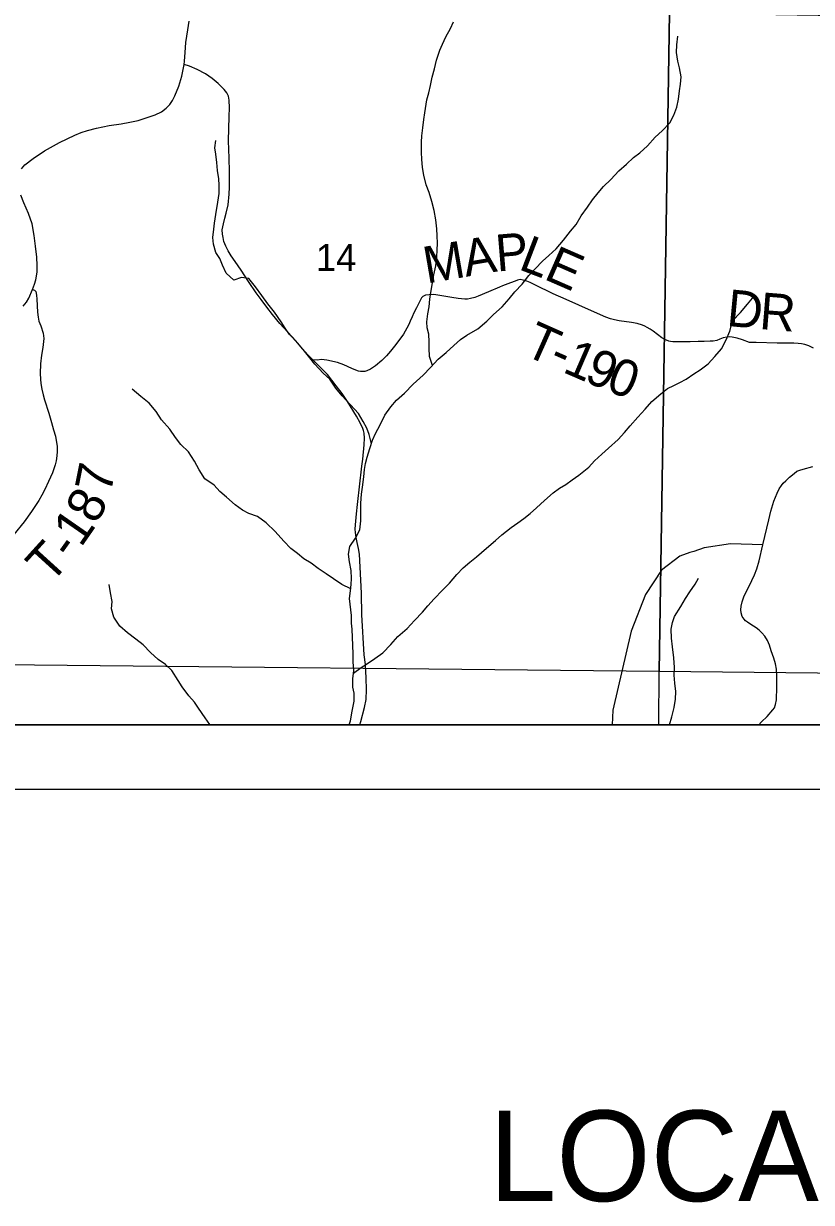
# Model space of a CAD drawing. Extents: x 0 to 34, y -8.9 to 22.
# Drawn here: x 25.687 to 26.904, y 6.366 to 8.187 of the extents above; entities that cross this region are included whole.
import ezdxf

# ---------------------------------------------------------------- set-up
doc = ezdxf.new("R2010")
doc.units = 0
for name, color, linetype in [('GM_X_Corporation', 7, 'Continuous'), ('GM_X_County_Road', 7, 'Continuous'), ('GM_X_Minor_River', 7, 'Continuous'), ('GM_X_Section_Text', 7, 'Continuous'), ('GM_X_State_Route', 7, 'Continuous'), ('GM_X_Township_Road', 7, 'Continuous'), ('GM_X_Township_Road_Text', 7, 'Continuous'), ('SH_Data', 7, 'Continuous'), ('SH_Text', 7, 'Continuous')]:
    doc.layers.add(name, color=color, linetype=linetype)

msp = doc.modelspace()

# ---------------------------------------------------------------- linework, layer by layer
at = {"layer": 'GM_X_Corporation'}
for points in [[(23.7167, 11.9654), (23.7167, 7.104), (28.7046, 7.104), (28.7123, 8.2818), (28.7238, 9.1729), (28.7308, 9.4444), (28.7377, 10.2012)], [(24.1844, 10.755), (24.1596, 9.2636), (24.0743, 9.2644), (23.7167, 9.2682), (23.7167, 7.104), (28.7046, 7.104), (28.7123, 8.2818), (28.7238, 9.1729), (28.7308, 9.4444), (28.7377, 10.2012)]]:
    msp.add_lwpolyline(points, dxfattribs=at)
for points in [[(25.6692, 8.2169), (26.6846, 8.2041), (26.6684, 7.1864), (25.6523, 7.1969)], [(26.6846, 8.2041), (27.7031, 8.1879), (27.6975, 7.1757), (26.6684, 7.1864)], [(25.6521, 7.104), (26.6681, 7.104), (26.6684, 7.1864), (25.6523, 7.1969)]]:
    msp.add_lwpolyline(points, close=True, dxfattribs=at)
at = {"layer": 'GM_X_County_Road'}
msp.add_lwpolyline([(26.206, 7.104), (26.2077, 7.1091), (26.2134, 7.1305), (26.2158, 7.1431), (26.2164, 7.1587), (26.216, 7.1759), (26.2148, 7.197), (26.213, 7.2119), (26.2093, 7.2739), (26.2085, 7.3075), (26.2055, 7.3679), (26.2043, 7.3764), (26.2021, 7.3857), (26.2003, 7.3935), (26.1992, 7.4009), (26.199, 7.4061), (26.1993, 7.4128), (26.2011, 7.43), (26.2027, 7.4445), (26.2059, 7.4764), (26.2085, 7.4988), (26.2091, 7.5035), (26.2107, 7.5147), (26.213, 7.5366), (26.2135, 7.5467), (26.2127, 7.5548), (26.2117, 7.5588), (26.2107, 7.5619), (26.2067, 7.5706), (26.2009, 7.5809), (26.1868, 7.6037), (26.1787, 7.616), (26.1696, 7.6279), (26.1563, 7.6451), (26.143, 7.6588), (26.1334, 7.6678), (26.126, 7.6755), (26.1173, 7.6851), (26.107, 7.6973), (26.0826, 7.7241), (26.0711, 7.7379), (26.0624, 7.7491), (26.0535, 7.761), (26.0457, 7.7715), (26.0343, 7.7887), (26.0228, 7.8063), (26.0135, 7.8199), (26.0073, 7.8285), (26.0028, 7.8363), (25.9988, 7.8438), (25.996, 7.8509), (25.9948, 7.8567), (25.9939, 7.862), (25.9936, 7.8687), (25.9952, 7.8779), (25.9975, 7.8867), (25.9997, 7.8943), (26.0024, 7.9074), (26.0042, 7.9241), (26.0046, 7.9347), (26.0046, 7.9442), (26.0045, 7.959), (26.0041, 7.9793), (26.0034, 8.0065), (26.0043, 8.0441), (26.0048, 8.0574), (26.0043, 8.069), (26.0031, 8.0755), (26.0006, 8.0806), (25.9965, 8.0856), (25.987, 8.0948), (25.9777, 8.1026), (25.9677, 8.1097), (25.9546, 8.1165), (25.943, 8.1217), (25.9346, 8.1244)], dxfattribs=at)
at = {"layer": 'GM_X_Minor_River'}
for points in [[(26.3183, 7.6594), (26.314, 7.6733), (26.3135, 7.6858), (26.3131, 7.6957), (26.3127, 7.7075), (26.3104, 7.7173), (26.3097, 7.7268), (26.3112, 7.739), (26.313, 7.7496), (26.3145, 7.7614), (26.316, 7.772), (26.3186, 7.7868), (26.3205, 7.799), (26.3235, 7.813), (26.325, 7.8271), (26.3257, 7.8373), (26.3261, 7.848), (26.3257, 7.8593), (26.3253, 7.8704), (26.3237, 7.884), (26.321, 7.8984), (26.3176, 7.9125), (26.313, 7.9265), (26.3088, 7.9382), (26.305, 7.9534), (26.3027, 7.9652), (26.3019, 7.9781), (26.3015, 7.9883), (26.3015, 8.0043), (26.3018, 8.0138), (26.3033, 8.0263), (26.3048, 8.0392), (26.3067, 8.0498), (26.3097, 8.0696), (26.3127, 8.0806), (26.3153, 8.092), (26.3179, 8.1045), (26.3217, 8.1174), (26.3247, 8.1311), (26.3296, 8.1463), (26.3338, 8.1558), (26.339, 8.1669), (26.3462, 8.1798), (26.3508, 8.19)], [(26.5094, 7.8394), (26.5207, 7.8528), (26.5317, 7.8665), (26.5404, 7.8771), (26.548, 7.8904), (26.5578, 7.9037), (26.5654, 7.9152), (26.5745, 7.9262), (26.5824, 7.9357), (26.5938, 7.9464), (26.6063, 7.9601), (26.618, 7.97), (26.629, 7.9806), (26.6388, 7.9875), (26.6506, 7.9986), (26.6627, 8.0119), (26.6733, 8.0218), (26.685, 8.0343), (26.6914, 8.0461), (26.696, 8.0583), (26.6986, 8.0708), (26.7001, 8.0837), (26.7016, 8.0936), (26.7027, 8.1054), (26.7, 8.119), (26.6973, 8.1293), (26.6954, 8.1429), (26.6958, 8.1547), (26.6976, 8.168)], [(26.2241, 7.5382), (26.2205, 7.5523), (26.2167, 7.5622), (26.2113, 7.5728), (26.2041, 7.5849), (26.179, 7.6121), (26.1691, 7.6243), (26.1596, 7.6383), (26.1493, 7.6474), (26.1368, 7.6614), (26.1288, 7.6712), (26.1208, 7.6814), (26.1105, 7.6939), (26.0976, 7.7072), (26.0907, 7.717), (26.0843, 7.7265), (26.074, 7.7416), (26.0637, 7.7545), (26.0546, 7.7674), (26.0447, 7.7806), (26.0344, 7.7935), (26.0234, 7.795), (26.0113, 7.7911), (25.9995, 7.8017), (25.9941, 7.8142), (25.9896, 7.8245), (25.9838, 7.834), (25.98, 7.8468), (25.9789, 7.8571), (25.9804, 7.8696), (25.9815, 7.8791), (25.9837, 7.8924), (25.9867, 7.9114), (25.9886, 7.9247), (25.9889, 7.938), (25.9882, 7.9478), (25.9862, 7.9607), (25.9851, 7.9729), (25.9835, 7.9858), (25.982, 7.9953), (25.9835, 8.007)], [(26.1897, 7.104), (26.1915, 7.1104), (26.1941, 7.1252), (26.1975, 7.1404), (26.1975, 7.1529), (26.1955, 7.1624), (26.1955, 7.1749), (26.1966, 7.1878), (26.1958, 7.2011), (26.1958, 7.2133), (26.1954, 7.2269), (26.195, 7.2387), (26.1942, 7.2516), (26.1934, 7.2611), (26.1934, 7.2728), (26.1903, 7.2994), (26.1918, 7.3112), (26.1925, 7.3207), (26.1933, 7.3302), (26.1925, 7.3423), (26.1902, 7.3556), (26.1886, 7.3677), (26.1905, 7.3795), (26.1992, 7.3924), (26.206, 7.4054), (26.2079, 7.419), (26.2078, 7.4464), (26.2086, 7.4604), (26.21, 7.4714), (26.2123, 7.487), (26.2134, 7.4984), (26.2149, 7.5079), (26.2172, 7.5177), (26.2217, 7.5311), (26.2258, 7.5436), (26.2304, 7.5542), (26.2375, 7.5675), (26.2447, 7.5824), (26.2542, 7.5953), (26.2629, 7.6056), (26.275, 7.6166), (26.2886, 7.6303), (26.3041, 7.6441), (26.3151, 7.6559), (26.3269, 7.6688), (26.3394, 7.6791), (26.3515, 7.6901), (26.3617, 7.6993), (26.3716, 7.7058), (26.3882, 7.7157), (26.4026, 7.7279), (26.4128, 7.7378), (26.4261, 7.7496), (26.4371, 7.7621), (26.4458, 7.7732), (26.4571, 7.785), (26.467, 7.7983), (26.4772, 7.8086), (26.4882, 7.8204), (26.4984, 7.8292), (26.5094, 7.8394)], [(26.1963, 7.184), (26.2084, 7.1928), (26.2179, 7.1985), (26.2292, 7.2062), (26.2417, 7.2153), (26.2538, 7.2282), (26.2648, 7.2404), (26.2792, 7.2526), (26.2906, 7.2652), (26.3027, 7.2781), (26.311, 7.288), (26.3208, 7.2987), (26.3341, 7.312), (26.3447, 7.3231), (26.3561, 7.336), (26.3659, 7.3463), (26.3761, 7.3554), (26.3863, 7.3634), (26.4019, 7.3768), (26.4159, 7.389), (26.4257, 7.3973), (26.4401, 7.4091), (26.45, 7.416), (26.4595, 7.4229), (26.4693, 7.4305), (26.4791, 7.4393), (26.4913, 7.4507), (26.5049, 7.4625), (26.5144, 7.4697), (26.5246, 7.4755), (26.5341, 7.4823), (26.5443, 7.4896), (26.5602, 7.5021), (26.5689, 7.5117), (26.5803, 7.5223), (26.5905, 7.5315), (26.6053, 7.5448), (26.6151, 7.5555), (26.6238, 7.5657), (26.6356, 7.5794), (26.6469, 7.5916), (26.6571, 7.6034), (26.6711, 7.6156), (26.6814, 7.6236), (26.6912, 7.6282), (26.7007, 7.6328), (26.7106, 7.6381), (26.7223, 7.6465), (26.7318, 7.6523), (26.7443, 7.6618), (26.7545, 7.6732), (26.7651, 7.685), (26.7723, 7.6987), (26.7776, 7.7124), (26.7821, 7.728), (26.7942, 7.7413), (26.8052, 7.7538), (26.8154, 7.7664)], [(26.192, 7.3142), (26.1785, 7.3206), (26.1656, 7.3293), (26.1542, 7.3372), (26.1416, 7.3456), (26.131, 7.3535), (26.1196, 7.3607), (26.1097, 7.3686), (26.0995, 7.3765), (26.0888, 7.3875), (26.0755, 7.4027), (26.0614, 7.4163), (26.0481, 7.4257), (26.0348, 7.4306), (26.0249, 7.4355), (26.0135, 7.4438), (25.9999, 7.4556), (25.99, 7.4643), (25.9808, 7.4741), (25.9664, 7.4843), (25.958, 7.4979), (25.9504, 7.5116), (25.9413, 7.5256), (25.9295, 7.5369), (25.9215, 7.5479), (25.9124, 7.5608), (25.8998, 7.5752), (25.8914, 7.5881), (25.8804, 7.6009), (25.8678, 7.6115), (25.8542, 7.6225)], [(26.6848, 7.104), (26.6882, 7.1165), (26.6919, 7.1306), (26.6938, 7.1435), (26.6942, 7.1556), (26.693, 7.1685), (26.6918, 7.1807), (26.6922, 7.1928), (26.6914, 7.2076), (26.6895, 7.2243), (26.6879, 7.238), (26.6871, 7.2517), (26.689, 7.2619), (26.6924, 7.2714), (26.7022, 7.2866), (26.7094, 7.2992), (26.7162, 7.3094), (26.7242, 7.3212), (26.7294, 7.3307)], [(25.9747, 7.104), (25.9745, 7.1044), (25.9672, 7.1146), (25.9569, 7.1297), (25.9508, 7.1392), (25.9421, 7.149), (25.9314, 7.1627), (25.9253, 7.1725), (25.9155, 7.1877), (25.9059, 7.1971), (25.8945, 7.2047), (25.8824, 7.2157), (25.8713, 7.2274), (25.8599, 7.2365), (25.847, 7.2463), (25.8352, 7.2565), (25.8261, 7.2705), (25.8223, 7.2834), (25.8234, 7.2944), (25.8207, 7.3077), (25.8188, 7.3206)]]:
    msp.add_lwpolyline(points, dxfattribs=at)
at = {"layer": 'GM_X_State_Route'}
for points in [[(25.6831, 7.9629), (25.6886, 7.9691), (25.7015, 7.9791), (25.7191, 7.9909), (25.7418, 8.0038), (25.7656, 8.0148), (25.7753, 8.019), (25.7853, 8.0222), (25.7992, 8.0261), (25.8188, 8.0299), (25.8373, 8.0325), (25.8507, 8.0352), (25.8635, 8.0379), (25.8758, 8.0418), (25.8901, 8.0463), (25.8998, 8.0513), (25.9071, 8.0568), (25.9123, 8.0626), (25.9164, 8.0686), (25.9203, 8.076), (25.9266, 8.091), (25.9312, 8.1063), (25.9346, 8.1244), (25.9353, 8.1292), (25.9361, 8.1426), (25.937, 8.158), (25.9402, 8.1778), (25.9423, 8.1912)], [(25.686, 7.7506), (25.6887, 7.7539), (25.6909, 7.7571), (25.6945, 7.7634), (25.7004, 7.7764), (25.7034, 7.7849), (25.7053, 7.7915), (25.7074, 7.8036), (25.7075, 7.8138), (25.7068, 7.8264), (25.7049, 7.8433), (25.703, 7.8601), (25.7, 7.878), (25.6943, 7.8942), (25.687, 7.9107), (25.6822, 7.9226)]]:
    msp.add_lwpolyline(points, dxfattribs=at)
at = {"layer": 'GM_X_Township_Road'}
for points in [[(26.9071, 7.686), (26.8999, 7.6894), (26.8938, 7.6914), (26.8885, 7.6924), (26.8835, 7.6932), (26.8766, 7.6936), (26.8639, 7.6936), (26.851, 7.6938), (26.8186, 7.6949), (26.8081, 7.6946), (26.7972, 7.6986), (26.7894, 7.7016), (26.7814, 7.7032), (26.777, 7.7034), (26.7732, 7.703), (26.7676, 7.7017), (26.7625, 7.6996), (26.758, 7.698), (26.7523, 7.6969), (26.7473, 7.6966), (26.7384, 7.6963), (26.7291, 7.6963), (26.7166, 7.6957), (26.7074, 7.6955), (26.6986, 7.6956), (26.6896, 7.6956), (26.6862, 7.6961), (26.6834, 7.6969), (26.6775, 7.6994), (26.6729, 7.7019), (26.6663, 7.7072), (26.6595, 7.7121), (26.6547, 7.7153), (26.65, 7.7179), (26.6465, 7.7198), (26.643, 7.7213), (26.6345, 7.7241), (26.626, 7.7258), (26.6148, 7.7271), (26.6103, 7.7275), (26.6068, 7.728), (26.5995, 7.7297), (26.5932, 7.7311), (26.5863, 7.7337), (26.5643, 7.7434), (26.525, 7.761), (26.5051, 7.7697), (26.4764, 7.7838), (26.4693, 7.7873), (26.464, 7.7896), (26.4585, 7.7912), (26.454, 7.792), (26.4498, 7.7909), (26.446, 7.7893), (26.4387, 7.7867), (26.4268, 7.7822), (26.4221, 7.7803), (26.405, 7.7731), (26.3891, 7.7663), (26.3839, 7.7644), (26.377, 7.7626), (26.3723, 7.7619), (26.3685, 7.7618), (26.3578, 7.7628), (26.3483, 7.764), (26.3204, 7.7687), (26.3135, 7.7686), (26.3078, 7.7676), (26.3035, 7.7658), (26.3013, 7.7638), (26.2939, 7.7485), (26.2896, 7.7404), (26.2868, 7.7344), (26.2841, 7.7279), (26.2817, 7.7225), (26.2789, 7.7167), (26.2735, 7.7076), (26.2666, 7.6979), (26.2598, 7.6889), (26.2537, 7.6811), (26.2473, 7.6741), (26.2399, 7.6667), (26.2301, 7.6587), (26.2224, 7.6536), (26.2169, 7.6508), (26.2136, 7.6501), (26.2109, 7.6498), (26.2073, 7.6499), (26.204, 7.6505), (26.2, 7.6518), (26.194, 7.6543), (26.1813, 7.6602), (26.1718, 7.6636), (26.1553, 7.6673), (26.1471, 7.6684), (26.1402, 7.6675), (26.1334, 7.6678)], [(25.7004, 7.7764), (25.7032, 7.7756), (25.7056, 7.7737), (25.7066, 7.7678), (25.7071, 7.7616), (25.7079, 7.7418), (25.7091, 7.7341), (25.7103, 7.7279), (25.7132, 7.7202), (25.717, 7.7092), (25.7179, 7.7009), (25.7164, 7.687), (25.7144, 7.675), (25.7126, 7.6617), (25.712, 7.6469), (25.7126, 7.6378), (25.7132, 7.6315), (25.7149, 7.6224), (25.7166, 7.6139), (25.7187, 7.6059), (25.7254, 7.5855), (25.7297, 7.5712), (25.7329, 7.56), (25.736, 7.5498), (25.737, 7.5432), (25.7382, 7.5345), (25.7383, 7.5263), (25.7381, 7.5194), (25.7369, 7.5117), (25.7355, 7.5057), (25.731, 7.4934), (25.7249, 7.4797), (25.7196, 7.4678), (25.7146, 7.4587), (25.7099, 7.4508), (25.6989, 7.4334), (25.6876, 7.4177), (25.6714, 7.3978)], [(26.8226, 7.104), (26.8269, 7.1086), (26.8355, 7.1166), (26.8444, 7.1269), (26.8467, 7.1301), (26.8486, 7.1354), (26.8497, 7.1428), (26.8504, 7.1624), (26.8504, 7.1807), (26.85, 7.1898), (26.8482, 7.1984), (26.8456, 7.2072), (26.8417, 7.2185), (26.839, 7.2268), (26.8362, 7.2342), (26.8318, 7.2409), (26.8274, 7.2463), (26.8232, 7.2502), (26.8184, 7.2538), (26.8143, 7.2563), (26.8101, 7.2591), (26.8049, 7.2625), (26.802, 7.2647), (26.8002, 7.2672), (26.797, 7.2713), (26.7955, 7.2769), (26.7949, 7.2816), (26.7952, 7.2873), (26.7967, 7.2938), (26.7994, 7.3015), (26.812, 7.327), (26.8158, 7.3357), (26.8194, 7.345), (26.8232, 7.3576), (26.8287, 7.382), (26.8379, 7.4209), (26.8414, 7.4341), (26.8456, 7.4495), (26.8509, 7.462), (26.8541, 7.4684), (26.8575, 7.4737), (26.8601, 7.4772), (26.8642, 7.4812), (26.8702, 7.4866), (26.877, 7.4925), (26.8816, 7.4957), (26.886, 7.4976), (26.8909, 7.4992), (26.9059, 7.5033)], [(26.8287, 7.382), (26.7789, 7.3836), (26.7382, 7.3773), (26.7222, 7.372)], [(26.7222, 7.372), (26.7162, 7.37), (26.7006, 7.3648), (26.6723, 7.3429), (26.6473, 7.3053), (26.6253, 7.2489), (26.5971, 7.1267), (26.5962, 7.104)]]:
    msp.add_lwpolyline(points, dxfattribs=at)
at = {"layer": 'SH_Data'}
for points in [[(23.6167, 14.004), (30.6167, 14.004), (30.6167, 7.004), (23.6167, 7.004)], [(23.7167, 13.904), (30.5167, 13.904), (30.5167, 7.104), (23.7167, 7.104)]]:
    msp.add_lwpolyline(points, close=True, dxfattribs=at)

# ---------------------------------------------------------------- texts
at = {"layer": 'GM_X_Section_Text'}
msp.add_text('14', height=0.04186, rotation=0, dxfattribs=at).set_placement((26.1384, 7.8051))
at = {"layer": 'GM_X_Township_Road_Text'}
for s, rotation, p in [('M', 9.7678, (26.3093, 7.7856)), ('A', 9.7073, (26.37, 7.7961)), ('P', 4.7522, (26.418, 7.8043)), ('L', 339.0422, (26.4496, 7.8085)), ('E', 336.3878, (26.4887, 7.7935)), ('D', 354.575, (26.7717, 7.7205)), ('R', 355.4077, (26.8224, 7.7157)), ('T', 335.9657, (26.4569, 7.6767)), ('1', 336.6202, (26.5177, 7.6497)), ('-', 336.1185, (26.4959, 7.6594)), ('9', 337.4374, (26.5507, 7.6355)), ('0', 338.6826, (26.5842, 7.6215)), ('7', 78.6999, (25.821, 7.4598)), ('8', 62.6028, (25.7992, 7.4124)), ('1', 55.2072, (25.7751, 7.3768)), ('T', 47.7799, (25.728, 7.3201)), ('-', 54.3877, (25.761, 7.3571))]:
    msp.add_text(s, height=0.0568, rotation=rotation, dxfattribs=at).set_placement(p)
at = {"layer": 'SH_Text'}
msp.add_text('LOCATION MAP', height=0.14, dxfattribs=at).set_placement((26.4057, 6.368))

doc.saveas('drawing.dxf')
